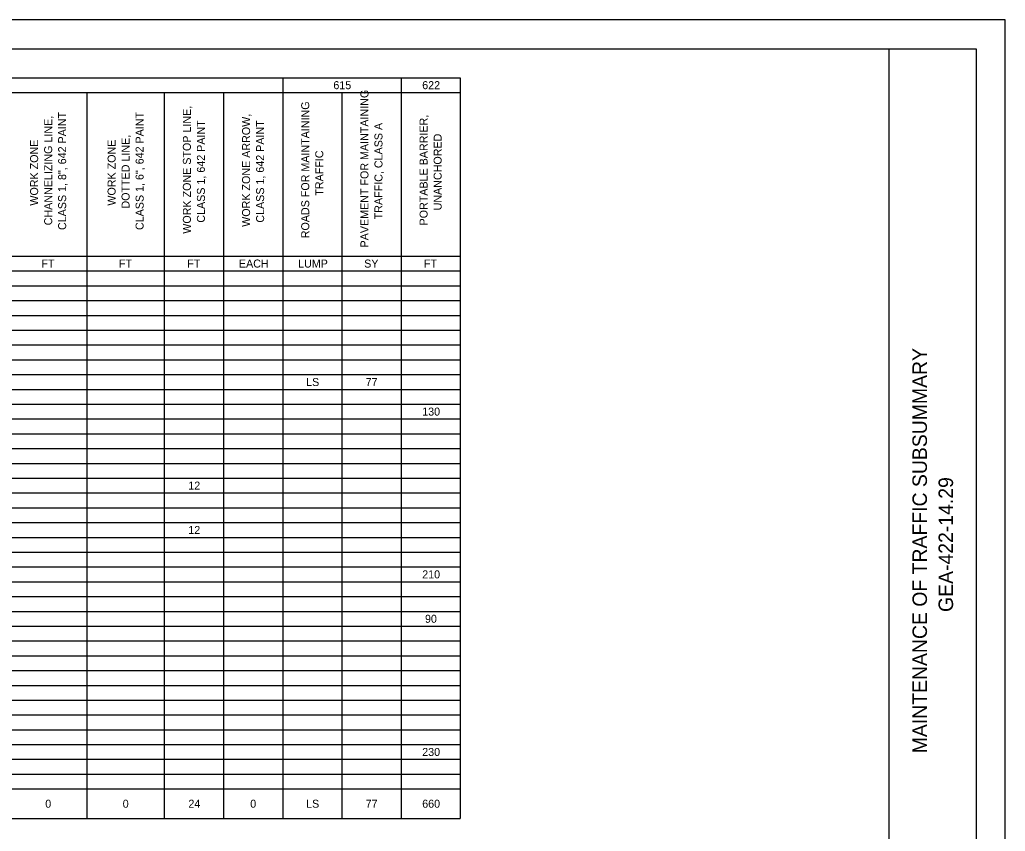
# Model space of a CAD drawing. Extents: x 0 to 34, y 0 to 22.
# Drawn here: x 17.01 to 34, y 8.01 to 22 of the extents above; entities that cross this region are included whole.
import ezdxf

# ---------------------------------------------------------------- set-up
doc = ezdxf.new("R2010")
doc.units = 0
for name, color, linetype in [('SH_Border', 7, 'Continuous'), ('SH_Cut_Line', 7, 'Continuous'), ('SH_Data', 7, 'Continuous'), ('SH_Text', 7, 'Continuous')]:
    doc.layers.add(name, color=color, linetype=linetype)

msp = doc.modelspace()

# ---------------------------------------------------------------- linework, layer by layer
at = {"layer": 'SH_Border'}
msp.add_line((32, 0.5), (32, 21.5), dxfattribs=at)
msp.add_lwpolyline([(1.5, 21.5), (33.5, 21.5), (33.5, 0.5), (1.5, 0.5)], close=True, dxfattribs=at)
at = {"layer": 'SH_Cut_Line'}
msp.add_lwpolyline([(0, 0), (34, 0), (34, 22), (0, 22)], close=True, dxfattribs=at)
at = {"layer": 'SH_Text'}
for p, q in [((2, 21), (24.605, 21)), ((21.545, 21), (21.545, 8.235)), ((23.585, 21), (23.585, 8.235)), ((24.605, 21), (24.605, 8.235)), ((8.045, 20.745), (24.605, 20.745)), ((18.17, 20.745), (18.17, 8.235)), ((19.505, 20.745), (19.505, 8.235)), ((20.525, 20.745), (20.525, 8.235)), ((22.565, 20.745), (22.565, 8.235)), ((8.045, 17.925), (24.605, 17.925)), ((2, 17.67), (24.605, 17.67)), ((2, 17.415), (24.605, 17.415)), ((2, 17.16), (24.605, 17.16)), ((2, 16.905), (24.605, 16.905)), ((2, 16.65), (24.605, 16.65)), ((2, 16.395), (24.605, 16.395)), ((2, 16.14), (24.605, 16.14)), ((2, 15.885), (24.605, 15.885)), ((2, 15.63), (24.605, 15.63)), ((2, 15.375), (24.605, 15.375)), ((2, 15.12), (24.605, 15.12)), ((2, 14.865), (24.605, 14.865)), ((2, 14.61), (24.605, 14.61)), ((2, 14.355), (24.605, 14.355)), ((2, 14.1), (24.605, 14.1)), ((2, 13.845), (24.605, 13.845)), ((2, 13.59), (24.605, 13.59)), ((2, 13.335), (24.605, 13.335)), ((2, 13.08), (24.605, 13.08)), ((2, 12.825), (24.605, 12.825)), ((2, 12.57), (24.605, 12.57)), ((2, 12.315), (24.605, 12.315)), ((2, 12.06), (24.605, 12.06)), ((2, 11.805), (24.605, 11.805)), ((2, 11.55), (24.605, 11.55)), ((2, 11.295), (24.605, 11.295)), ((2, 11.04), (24.605, 11.04)), ((2, 10.785), (24.605, 10.785)), ((2, 10.53), (24.605, 10.53)), ((2, 10.275), (24.605, 10.275)), ((2, 10.02), (24.605, 10.02)), ((2, 9.765), (24.605, 9.765)), ((2, 9.51), (24.605, 9.51)), ((2, 9.255), (24.605, 9.255)), ((2, 9), (24.605, 9)), ((2, 8.745), (24.605, 8.745)), ((2, 8.235), (24.605, 8.235))]:
    msp.add_line(p, q, dxfattribs=at)

# ---------------------------------------------------------------- texts
at = {"layer": 'SH_Data'}
for s, p in [('MAINTENANCE OF TRAFFIC SUBSUMMARY', (32.65, 9.359)), ('GEA-422-14.29', (33.1, 11.794))]:
    msp.add_text(s, height=0.25, rotation=90, dxfattribs=at).set_placement(p)
at = {"layer": 'SH_Text'}
for s, p in [('615', (22.419, 20.803)), ('622', (23.95, 20.803)), ('FT', (17.388, 17.729)), ('FT', (18.723, 17.729)), ('FT', (19.9, 17.729)), ('EACH', (20.791, 17.729)), ('LUMP', (21.811, 17.729)), ('SY', (22.95, 17.729)), ('FT', (23.98, 17.729)), ('LS', (21.949, 15.688)), ('77', (22.975, 15.688)), ('130', (23.95, 15.178)), ('12', (19.918, 13.903)), ('12', (19.918, 13.138)), ('210', (23.95, 12.373)), ('90', (23.998, 11.608)), ('230', (23.95, 9.313)), ('0', (17.453, 8.421)), ('0', (18.788, 8.421)), ('24', (19.92, 8.421)), ('0', (20.986, 8.421)), ('LS', (21.949, 8.421)), ('77', (22.975, 8.421)), ('660', (23.95, 8.421))]:
    msp.add_text(s, height=0.138, dxfattribs=at).set_placement(p)
for s, p in [('PAVEMENT FOR MAINTAINING ', (23.023, 18.076)), ('ROADS FOR MAINTAINING ', (22.003, 18.234)), ('CLASS 1, 8", 642 PAINT', (17.813, 18.376)), ('CLASS 1, 6", 642 PAINT', (19.148, 18.376)), ('WORK ZONE STOP LINE, ', (19.963, 18.312)), ('CHANNELIZING LINE,', (17.572, 18.457)), ('CLASS 1, 642 PAINT', (20.205, 18.503)), ('WORK ZONE ARROW, ', (20.983, 18.431)), ('CLASS 1, 642 PAINT', (21.225, 18.503)), ('TRAFFIC, CLASS A', (23.265, 18.561)), ('PORTABLE BARRIER, ', (24.043, 18.455)), ('WORK ZONE', (17.33, 18.796)), ('WORK ZONE', (18.665, 18.796)), ('DOTTED LINE,', (18.906, 18.746)), ('UNANCHORED', (24.285, 18.714)), ('TRAFFIC', (22.245, 18.968))]:
    msp.add_text(s, height=0.138, rotation=90, dxfattribs=at).set_placement(p)

doc.saveas('drawing.dxf')
